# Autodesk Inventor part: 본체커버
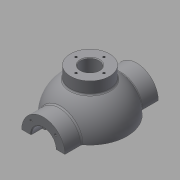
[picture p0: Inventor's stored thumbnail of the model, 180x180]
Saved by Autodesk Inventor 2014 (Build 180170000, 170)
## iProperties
Created: 2015-12
Part Number: 본체커버
Material: 일반
Document SubType Name: Modeling
Designer: mduedu
Density: 1 g/cm^3
Mass: 201.945 g
Surface Area: 428.16 cm^2
Volume: 201.945 cm^3
Appearance: 기본값
Author: mduedu
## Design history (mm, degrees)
sketch "스케치1"
  geometry: L1 (-53, 0)-(53, 0); A1 r 53 centre (0, 0) between (53, 0) and (-53, 0); 2 further points
  constraints: 2 coincident, 2 end point, 2 point on circle, 1 centre point, 1 horizontal, 1 midpoint
  dimensions: "d0" = 53 radius of A1
revolve "회전1" sketch "스케치1" stored, may be unused: angle "d2" = 90 deg
feature "쉘1" dims "d11" = 10
node "작업 평면1"
sketch "스케치2"
  geometry: C1 r 31 at (0, 0); 1 further point
  constraints: 1 centre point, 1 coincident
  dimensions: "d4" = 62 diameter of C1
extrude "돌출1" join sketch "스케치2" stored distance "d5" = 10; taper "d6" = 0 deg
hole "구멍1" diameter "d14" = 35; stored, may be unused: countersink angle "d18" = 90 deg, drill point angle "d20" = 0 deg; dims "d12" = 10, "d13" = 10, "d15" = 6, "d16" = 4, "d17" = 2, "d19" = 16
hole "구멍2" diameter "d23" = 27; stored, may be unused: countersink angle "d27" = 90 deg, drill point angle "d29" = 0 deg; dims "d21" = 10, "d22" = 10, "d24" = 6, "d25" = 4, "d26" = 2, "d28" = 16
fillet "모깎기1" dims "d30" = 0.3
chamfer "모따기1" distance "d40" = 1; stored, may be unused: second distance "d41" = 2, angle "d42" = 45 deg
sketch "스케치4"
  geometry: L1 (0, 0)-(0, -25); L2 (0, 0)-(-17.678, -17.678); A1 r 25 centre (0, 0) between (-17.678, -17.678) and (0, -25); 1 further point
  constraints: 4 end point, 2 point on circle, 1 centre point, 1 coincident, 1 vertical
  dimensions: "d43" = 50 diameter of A1; "d47" = 45 deg angle of L1 L2
hole "구멍4" sketch "스케치4" at (-17.678, -17.678) diameter "d49" = 3.242; stored, may be unused: countersink angle "d53" = 90 deg, drill point angle "d55" = 118 deg; dims "d50" = 11, "d51" = 4, "d52" = 2, "d54" = 13
node "작업 평면3"
sketch "스케치6"
  geometry: C1 r 65 at (0, 0); 1 further point
  constraints: 1 centre point, 1 coincident
  dimensions: "d78" = 130 diameter of C1
extrude "돌출3" join sketch "스케치6" distance "d80" = 10; taper "d81" = 0 deg
sketch "스케치7"
  geometry: C1 r 20 at (0, 0); 1 further point
  constraints: 1 centre point, 1 coincident
  dimensions: "d82" = 40 diameter of C1
extrude "돌출4" join sketch "스케치7" stored distance "d84" = 10; taper "d85" = 0 deg
sketch "스케치8"
  geometry: 2 further points
  constraints: 1 coincident
hole "구멍6" sketch "스케치8" at (0, 0) diameter "d86" = 20; stored, may be unused: countersink angle "d90" = 90 deg, drill point angle "d92" = 118 deg; dims "d87" = 7, "d88" = 40, "d89" = 5, "d91" = 10
fillet "모깎기2" dims "d93" = 0.3
sketch "스케치9"
  geometry: L1 (65, -75)-(-65, -75) reference; L2 (-45, -75)-(-38.245, -36.692); A1 r 53 centre (0, 0) between (42.988, 31) and (42.988, -31) reference; 1 further point
  constraints: 2 end point, 1 point on circle, 1 point on line
  dimensions: "d94" = 45 horizontal distance of L2.start point (0, 0); "d95" = 80 deg angle of L2 L1
feature "리브1" sketch "스케치9" dims "d96" = 1, "d97" = 8, "d98" = 0, "d99" = 0, "d100" = 1, "d101" = 1
sketch "스케치10"
  geometry: L1 (0, 0)-(0, -55); L2 (0, 0)-(-38.891, -38.891); A1 r 55 centre (0, 0) between (0, -55) and (-38.891, -38.891); 2 further points
  constraints: 4 end point, 2 coincident, 2 point on circle, 1 centre point, 1 vertical
  dimensions: "d105" = 110 diameter of A1; "d107" = 45 deg angle of L1 L2
hole "구멍7" sketch "스케치10" at (-38.891, -38.891) diameter "d109" = 10; stored, may be unused: countersink angle "d113" = 90 deg, drill point angle "d115" = 118 deg; dims "d110" = 7, "d111" = 40, "d112" = 5, "d114" = 10
fillet "모깎기3" dims "d120" = 3
fillet "모깎기4" dims "d121" = 3, "d122" = 3
fillet "모깎기5" dims "d123" = 3
fillet "모깎기6" dims "d124" = 3
sketch "스케치11"
  geometry: C1 r 5 at (-38.891, 38.891) reference; C2 r 5 at (38.891, 38.891) reference; C3 r 5 at (38.891, -38.891) reference; C4 r 5 at (-38.891, -38.891) reference; C5 r 20 at (0, 0) reference; C6 r 65 at (0, 0) reference; 1 further point
  constraints: 3 other
feature "엠보싱1" sketch "스케치11" dims "d125" = 0.5, "d126" = 0
sketch "스케치12"
  geometry: L1 (0, 100)-(0, -100); L2 (0, 100)-(-150, 100); L3 (-150, 100)-(-150, -100); L4 (-150, -100)-(0, -100); 2 further points
  constraints: 8 end point, 3 perpendicular, 1 coincident, 1 midpoint, 1 vertical
  dimensions: "d127" = 200 distance of L2.end L3.end; "d129" = 150 distance of L3.end L1.end
extrude "돌출5" cut sketch "스케치12" stored distance "d130" = 10; taper "d131" = 0 deg
node "작업 평면4"
sketch "스케치16"
  geometry: C1 r 28 at (0, 0); 1 further point
  constraints: 1 centre point, 1 coincident
  dimensions: "d148" = 56 diameter of C1
extrude "돌출9" join sketch "스케치16" stored distance "d150" = 5; taper "d151" = 0 deg
hole "구멍8" diameter "d154" = 26; stored, may be unused: countersink angle "d158" = 90 deg, drill point angle "d160" = 118 deg; dims "d152" = 10, "d153" = 10, "d155" = 6, "d156" = 4, "d157" = 2, "d159" = 8
sketch "스케치17" dims "d161" = 40
  geometry: 3 further points
  constraints: 2 vertical alignment, 1 coincident, 2 other
hole "구멍9" sketch "스케치17" at (0, 20) diameter "d163" = 3.242; stored, may be unused: countersink angle "d167" = 90 deg, drill point angle "d169" = 118 deg; dims "d164" = 8, "d165" = 4, "d166" = 2, "d168" = 10
fillet "모깎기11" dims "d173" = 3
chamfer "모따기2" distance "d174" = 1; stored, may be unused: second distance "d175" = 2, angle "d176" = 45 deg
node "솔리드1"
mirror "대칭1"
mirror "대칭2"
pattern_circular "원형 패턴1" dims angle "d57" = 360 deg
mirror "대칭3"
pattern_circular "원형 패턴3" dims angle "d103" = 360 deg
pattern_circular "원형 패턴4" dims "d40" = 1, angle "d118" = 360 deg
pattern_circular "원형 패턴5" dims angle "d171" = 360 deg
node "투영된 루프1"
other parameters: "d3" = 67, "d77" = -85, "d147" = 62
